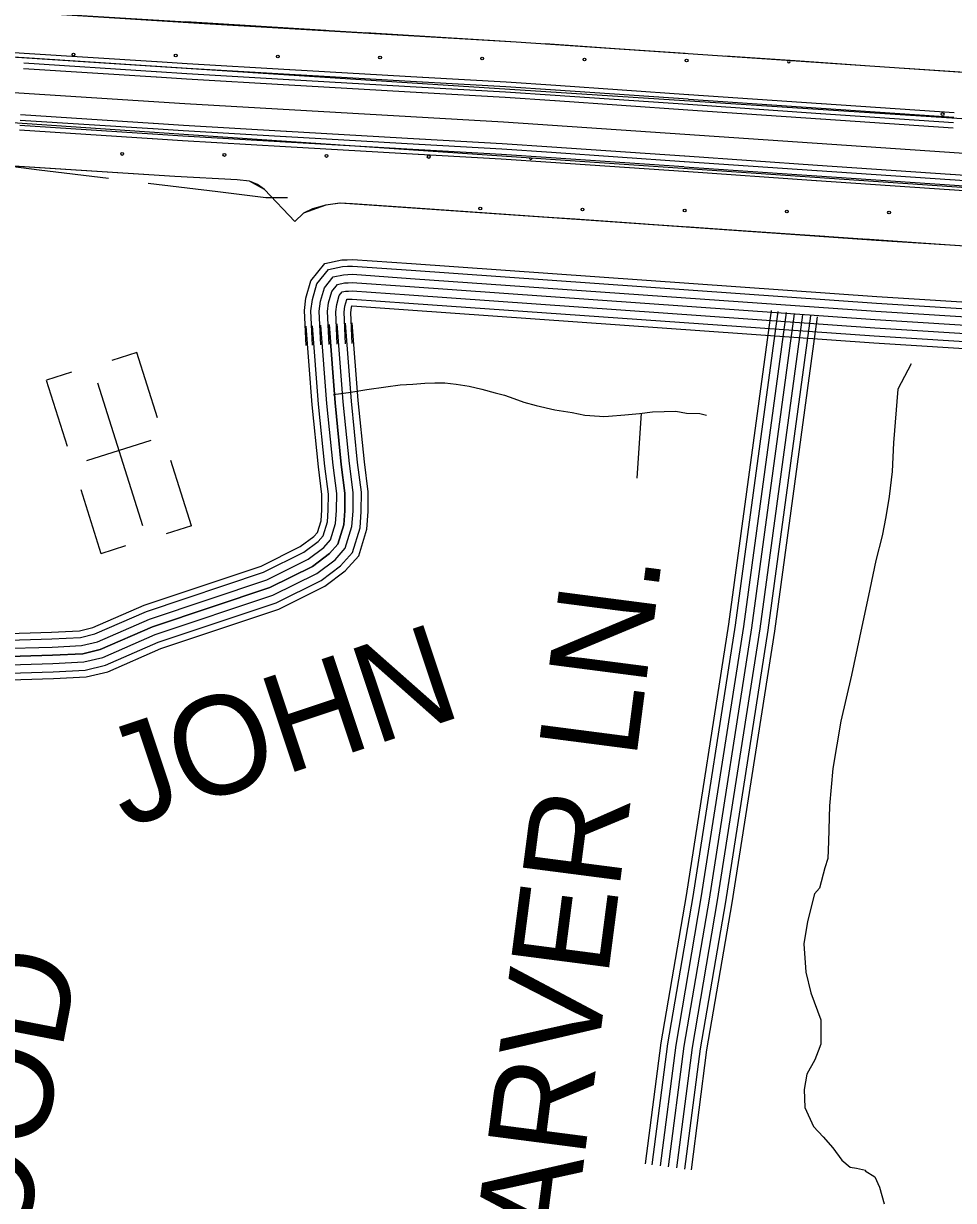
# Model space of a CAD drawing. Extents: x 1788175 to 1969470, y 584502 to 738744.
# Drawn here: x 1804703 to 1808203, y 664174 to 668600 of the extents above; entities that cross this region are included whole.
import ezdxf

# ---------------------------------------------------------------- set-up
doc = ezdxf.new("R2010")
doc.units = 0
for name, color, linetype in [('DESIGN - EROSION CONTROL - Devices', 7, 'Continuous'), ('DESIGN - ROW - Right-of-Way and Easement Labels', 7, 'Continuous'), ('DESIGN - SCRATCH - User 1', 7, 'Continuous'), ('DESIGN - TRANSPORTATION - Text', 7, 'Continuous'), ('DESIGN - UTILITIES - Cable (Underground) with Text', 7, 'Continuous'), ('SURVEY - CENTERLINE - Preliminary', 7, 'Continuous'), ('SURVEY - TRANSPORTATION - Roads', 7, 'Continuous'), ('SURVEY - VEGETATION - Features with Text', 7, 'Continuous')]:
    doc.layers.add(name, color=color, linetype=linetype)

msp = doc.modelspace()

# ---------------------------------------------------------------- linework, layer by layer
at = {"layer": 'DESIGN - EROSION CONTROL - Devices'}
for centre in [(1804891.6, 668483.1), (1805276.1, 668479.4), (1805660.7, 668475.6), (1806045.2, 668471.9), (1806429.8, 668468.2), (1806814.4, 668464.4), (1807198.9, 668460.7), (1808162.2, 668259.1), (1805074.6, 668109), (1805459.2, 668105.2), (1805843.7, 668101.5), (1806228.3, 668097.8), (1806422.4, 667903.6), (1806807, 667899.9), (1807191.5, 667896.1), (1807576.1, 667892.4), (1807960.6, 667888.7)]:
    msp.add_circle(centre, 5.28, dxfattribs=at)
for centre, start, end in [((1807583.5, 668457), 135.7944, 36.4425), ((1806612.8, 668094), 166.1356, 6.0817)]:
    msp.add_arc(centre, 5.28, start, end, dxfattribs=at)
at = {"layer": 'DESIGN - SCRATCH - User 1'}
for points in [[(1808664.9, 668387), (1806557.8, 668530), (1805384.9, 668598.1), (1804466.6, 668656.6), (1803677.1, 668706.8), (1802620.2, 668775.3), (1800681.4, 668914), (1800770.3, 668727.1)], [(1800770.3, 668727.1), (1809434.2, 668164.9), (1810234.9, 668118.5)], [(1800969.8, 668307.9), (1800885.7, 668484.5), (1810019.5, 667863.2)], [(1805724, 667855), (1805610.1, 667975.2), (1805583.5, 667994), (1805553.9, 668006.5), (1805507, 668011.2), (1805272.8, 668023.7), (1804393.1, 668080.1), (1803603.5, 668130.3), (1802569.9, 668197.2), (1800969.8, 668307.9)], [(1811666.5, 667588.8), (1811521.7, 667556.7), (1811453.2, 667549.4), (1811321.5, 667549.6), (1811097.5, 667563.7), (1810526.1, 667608.2), (1809694, 667671.1), (1807912.6, 667783), (1806161.4, 667906.7), (1805941.7, 667922), (1805893.4, 667924.4), (1805841, 667916.4), (1805790.9, 667902.7), (1805757, 667886.5), (1805724, 667855)]]:
    msp.add_lwpolyline(points, dxfattribs=at)
at = {"layer": 'DESIGN - TRANSPORTATION - Text'}
msp.add_lwpolyline([(1808044, 667319.3), (1807993.3, 667224.1), (1807977, 667022.3), (1807972.8, 666914.4), (1807960.6, 666820.5), (1807948.5, 666744.6), (1807934.4, 666672.7), (1807910.3, 666580.8), (1807888.1, 666472.9), (1807849.8, 666291.2), (1807819.6, 666149.3), (1807779.4, 665975.5), (1807749.1, 665797.7), (1807736.9, 665657.9), (1807732.6, 665524), (1807730.5, 665460.1), (1807718.5, 665424.1), (1807698.4, 665348.2), (1807680.3, 665326.3), (1807654.2, 665222.4), (1807640.1, 665138.5), (1807647.9, 665032.6), (1807665.8, 664954.7), (1807703.6, 664852.7), (1807703.5, 664800.8), (1807703.4, 664760.8), (1807693.4, 664734.8), (1807681.3, 664702.9), (1807651.3, 664649), (1807641.2, 664591), (1807643.1, 664523.1), (1807676.9, 664451.1), (1807712.9, 664413.1), (1807748.8, 664371.1), (1807782.7, 664325.1), (1807814.6, 664299.1), (1807838.6, 664295.1), (1807872.6, 664287.1), (1807870.6, 664285.1), (1807906.5, 664263), (1807924.5, 664223.1), (1807942.3, 664161.1)], dxfattribs=at)
at = {"layer": 'DESIGN - UTILITIES - Cable (Underground) with Text'}
for p, q in [((1805130.3, 667361.9), (1805035.2, 667331.9)), ((1805207.5, 667117.1), (1805130.2, 667361.9)), ((1804789.3, 667258.4), (1804867.8, 667009.7)), ((1804884.3, 667288.4), (1804789.9, 667258.6)), ((1805182.2, 667031.1), (1804940.4, 666954.7)), ((1805336, 666710.4), (1805258.2, 666956.5)), ((1804919.3, 666846.7), (1804995, 666606.9)), ((1805335.8, 666710.3), (1805240.9, 666680.4)), ((1804995.1, 666606.9), (1805088.8, 666636.5))]:
    msp.add_line(p, q, dxfattribs=at)
msp.add_lwpolyline([(1804982.1, 667248.6), (1805151.6, 666711.7)], dxfattribs=at)
at = {"layer": 'SURVEY - CENTERLINE - Preliminary'}
for points in [[(1820911.6, 669976.1), (1819959.6, 669862.9), (1819285.6, 669778.9), (1818471.7, 669687.3), (1818197.7, 669646.1), (1817901.7, 669609), (1817647.6, 669569.8), (1817303.6, 669516.8), (1816595.4, 669363), (1813251.8, 668401.6), (1812821.5, 668274.9), (1812669.5, 668231.4), (1812114.7, 668085.6), (1811965.2, 668057.6), (1811725.2, 668016.3), (1811385.2, 667981.3), (1811049.3, 667954.3), (1810455.5, 667960), (1806509.9, 668228.8), (1805310.6, 668298.1), (1804431.1, 668354.5), (1803641.6, 668404.7), (1802608.2, 668471.6), (1798199.8, 668776.1)], [(1804205.4, 668503.1), (1804439.6, 668488.2), (1804704.5, 668471.2)], [(1804206.5, 668520.6), (1804440.8, 668505.7), (1804705.6, 668488.7)], [(1804705.4, 668471.2), (1805204.4, 668439.2)], [(1804706.5, 668488.7), (1805205.5, 668456.6)], [(1805206.4, 668456.6), (1805319.8, 668449.3), (1805704.6, 668427.1)], [(1804703.7, 668430.9), (1805202.7, 668398.9)], [(1804704.1, 668451.2), (1805203.1, 668419.2)], [(1805204, 668419.2), (1805317.5, 668411.9), (1805702.4, 668389.6)], [(1805205.3, 668439.1), (1805318.7, 668431.8), (1805703.6, 668409.6)], [(1805704.5, 668409.5), (1806203.6, 668380.7)], [(1805705.5, 668427), (1806204.6, 668398.2)], [(1805203.6, 668398.9), (1805316.3, 668391.6), (1805702.2, 668369.3)], [(1805703.1, 668369.3), (1806202.2, 668340.4)], [(1805703.3, 668389.6), (1806202.5, 668360.7)], [(1806204.5, 668380.6), (1806518.3, 668362.5), (1806705, 668349.8)], [(1806205.6, 668398.1), (1806519.4, 668380), (1806706.2, 668367.3)], [(1806707.1, 668367.2), (1807205.9, 668333.2)], [(1806203.1, 668340.4), (1806515.8, 668322.3), (1806703.1, 668309.5)], [(1806203.4, 668360.7), (1806517.1, 668342.6), (1806703.6, 668329.8)], [(1806704.5, 668329.8), (1807203.4, 668295.8)], [(1806705.9, 668349.7), (1807204.7, 668315.8)], [(1807206.8, 668333.2), (1807705.7, 668299.2)], [(1806704, 668309.5), (1807202.9, 668275.5)], [(1807203.8, 668275.4), (1807702.6, 668241.4)], [(1807204.3, 668295.7), (1807703.1, 668261.7)], [(1807205.6, 668315.7), (1807704.5, 668281.7)], [(1807705.4, 668281.6), (1808204.2, 668247.7)], [(1807706.6, 668299.1), (1808205.4, 668265.1)], [(1804691.3, 668236.6), (1805190.2, 668204.6)], [(1804692.6, 668256.9), (1805191.5, 668224.8)], [(1807703.5, 668241.4), (1808202.4, 668207.4)], [(1807704, 668261.7), (1808202.9, 668227.7)], [(1804688.9, 668199.2), (1805187.8, 668167.2)], [(1804690, 668216.7), (1805189, 668184.6)], [(1805191.2, 668204.5), (1805304.4, 668197.3), (1805690.9, 668174.9)], [(1805192.4, 668224.8), (1805305.7, 668217.5), (1805692.1, 668195.2)], [(1805693, 668195.1), (1806192.2, 668166.3)], [(1805188.7, 668167.1), (1805302.2, 668159.8), (1805688.8, 668137.5)], [(1805189.9, 668184.6), (1805303.2, 668177.3), (1805689.8, 668155)], [(1805690.7, 668154.9), (1806189.8, 668126.1)], [(1805691.8, 668174.9), (1806191, 668146)], [(1806191.9, 668146), (1806503.6, 668128), (1806689.9, 668115.3)], [(1806193.1, 668166.2), (1806504.8, 668148.2), (1806691.3, 668135.5)], [(1805689.7, 668137.5), (1806188.8, 668108.6)], [(1806189.7, 668108.6), (1806501.2, 668090.6), (1806687.4, 668077.9)], [(1806190.7, 668126), (1806502.3, 668108), (1806688.5, 668095.3)], [(1806690.8, 668115.2), (1807189.6, 668081.2)], [(1806692.2, 668135.5), (1807191, 668101.5)], [(1807191.9, 668101.4), (1807690.8, 668067.4)], [(1806688.3, 668077.8), (1807187.1, 668043.8)], [(1806689.5, 668095.3), (1807188.3, 668061.3)], [(1807189.2, 668061.2), (1807688, 668027.2)], [(1807190.6, 668081.2), (1807689.4, 668047.2)], [(1807691.7, 668067.4), (1808190.5, 668033.4)], [(1807188, 668043.8), (1807686.8, 668009.8)], [(1807688.9, 668027.2), (1808187.8, 667993.2)], [(1807690.3, 668047.1), (1808189.1, 668013.1)], [(1808190.1, 668013.1), (1808688.9, 667979.1)], [(1808191.4, 668033.3), (1808690.3, 667999.3)], [(1807687.8, 668009.7), (1808186.6, 667975.7)], [(1808187.5, 667975.7), (1808686.3, 667941.7)], [(1808188.7, 667993.1), (1808687.5, 667959.1)]]:
    msp.add_lwpolyline(points, dxfattribs=at)
at = {"layer": 'SURVEY - TRANSPORTATION - Roads'}
for points in [[(1805766.5, 667388.4), (1805760.5, 667520.2), (1805766.3, 667566.4), (1805785, 667631.9), (1805837.3, 667697), (1805901, 667710.6), (1805922, 667711.2), (1805941.5, 667712.3), (1806163.6, 667696.9), (1807914.6, 667573.1), (1809696.1, 667461.3), (1810528.4, 667398.4), (1811099.7, 667353.8), (1811322.3, 667339.8), (1811450.9, 667339.7), (1811513.5, 667346.4), (1811898.5, 667449.7)], [(1805791.2, 667389.5), (1805785.3, 667519.3), (1805790.5, 667561.4), (1805807.4, 667620.3), (1805851.1, 667674.7), (1805903.9, 667686), (1805923, 667686.5), (1805941.3, 667687.5), (1806161.8, 667672.2), (1807912.9, 667548.5), (1809694.4, 667436.6), (1810526.5, 667373.7), (1811097.9, 667329.2), (1811321.5, 667315.1), (1811452.2, 667314.9), (1811518, 667322), (1811904.9, 667425.9)], [(1805822.1, 667390.9), (1805816.4, 667518), (1805821, 667555.2), (1805835.5, 667605.8), (1805868.3, 667646.7), (1805907.7, 667655.1), (1805924.2, 667655.6), (1805941.1, 667656.4), (1806159.7, 667641.3), (1807910.9, 667517.5), (1809692.3, 667405.7), (1810524.2, 667342.8), (1811095.7, 667298.2), (1811320.5, 667284.1), (1811453.8, 667283.9), (1811523.7, 667291.4), (1811912.9, 667395.9)], [(1805853.1, 667392.3), (1805847.5, 667516.8), (1805851.5, 667549), (1805863.5, 667591.2), (1805885.6, 667618.7), (1805911.4, 667624.2), (1805925.5, 667624.6), (1805940.8, 667625.4), (1806157.5, 667610.4), (1807908.8, 667486.6), (1809690.1, 667374.8), (1810521.8, 667311.9), (1811093.6, 667267.3), (1811319.5, 667253.1), (1811455.4, 667252.9), (1811529.4, 667260.9), (1811921, 667366)], [(1805853.1, 667392.3), (1805847.5, 667516.8), (1805851.5, 667549), (1805863.5, 667591.2), (1805885.6, 667618.7), (1805911.4, 667624.2), (1805925.5, 667624.6), (1805940.8, 667625.4), (1806157.5, 667610.4), (1807908.8, 667486.6), (1809690.1, 667374.8), (1810521.8, 667311.9), (1811093.6, 667267.3), (1811319.5, 667253.1), (1811455.4, 667252.9), (1811529.4, 667260.9), (1811921, 667366)], [(1805884.1, 667393.7), (1805878.5, 667515.6), (1805881.9, 667542.8), (1805891.6, 667576.7), (1805902.9, 667590.7), (1805915.1, 667593.3), (1805926.7, 667593.6), (1805940.6, 667594.3), (1806155.3, 667579.5), (1807906.7, 667455.7), (1809688, 667343.8), (1810519.4, 667281), (1811091.4, 667236.4), (1811318.5, 667222.1), (1811457.1, 667221.9), (1811535.1, 667230.3), (1811929, 667336)], [(1805915, 667395.2), (1805909.6, 667514.4), (1805912.4, 667536.6), (1805919.7, 667562.2), (1805919.9, 667562.4), (1805928, 667562.6), (1805940.3, 667563.3), (1806153.2, 667548.5), (1807904.7, 667424.7), (1809685.9, 667312.9), (1810517, 667250.1), (1811089.2, 667205.5), (1811317.5, 667191.1), (1811458.7, 667190.9), (1811540.8, 667199.7), (1811937, 667306.1)], [(1805940.7, 667396.3), (1805935.4, 667513.3), (1805937.7, 667531.4), (1805939.4, 667537.5), (1805940.1, 667537.5), (1806151.4, 667522.9), (1807903, 667399.1), (1809684.1, 667287.2), (1810515.1, 667224.4), (1811087.4, 667179.8), (1811316.7, 667165.4), (1811460.1, 667165.2), (1811545.6, 667174.4), (1811943.7, 667281.3)], [(1807517.1, 667520), (1807356.5, 666340.3), (1807196.9, 665320.9), (1807101.7, 664766.3), (1807042.7, 664311)], [(1807542.5, 667516.5), (1807381.9, 666336.5), (1807222.3, 665316.7), (1807127.1, 664762.5), (1807068.2, 664307.7)], [(1807573.3, 667512.3), (1807412.6, 666332), (1807252.9, 665311.7), (1807157.8, 664757.9), (1807098.9, 664303.7)], [(1807604, 667508.1), (1807443.3, 666327.6), (1807283.4, 665306.6), (1807188.5, 664753.2), (1807129.6, 664299.7)], [(1807604, 667508.1), (1807443.3, 666327.6), (1807283.4, 665306.6), (1807188.5, 664753.2), (1807129.6, 664299.7)], [(1807634.7, 667504), (1807474, 666323.1), (1807314, 665301.6), (1807219.1, 664748.6), (1807160.4, 664295.7)], [(1807665.4, 667499.8), (1807504.6, 666318.6), (1807344.6, 665296.6), (1807249.8, 664744), (1807191.1, 664291.7)], [(1807689.9, 667496.4), (1807529.1, 666315), (1807369, 665292.6), (1807274.2, 664740.3), (1807215.6, 664288.6)], [(1804606.1, 666304.5), (1804808.8, 666310.2), (1804913.7, 666315.7), (1804964.5, 666327.9), (1805157.2, 666412.1), (1805597.3, 666558.8), (1805744.9, 666632.4), (1805795.7, 666670.4), (1805809.4, 666685.6), (1805823, 666729.8), (1805825.7, 666770.7), (1805826.3, 666828.7), (1805813.1, 666931.9), (1805789.3, 667165.9), (1805766.6, 667460.9)], [(1804606.7, 666279.8), (1804809.7, 666285.6), (1804917.3, 666291.1), (1804972.4, 666304.4), (1805166, 666389), (1805606.7, 666535.9), (1805757.9, 666611.2), (1805812.5, 666652), (1805831.4, 666673.2), (1805847.4, 666725.3), (1805850.4, 666769.7), (1805851, 666830.2), (1805837.6, 666934.7), (1805813.9, 667168.1), (1805791.3, 667462.8)], [(1804607.5, 666248.8), (1804811, 666254.6), (1804921.7, 666260.3), (1804982.3, 666274.9), (1805177.2, 666360.1), (1805618.6, 666507.2), (1805774.2, 666584.7), (1805833.6, 666629.1), (1805859.1, 666657.6), (1805878.1, 666719.6), (1805881.4, 666768.5), (1805882, 666832), (1805868.4, 666938.2), (1805844.8, 667170.8), (1805822.2, 667465.2)], [(1805853.1, 667467.6), (1805875.7, 667173.6), (1805899.2, 666941.8), (1805913, 666833.8), (1805912.4, 666767.4), (1805908.8, 666714), (1805886.7, 666642), (1805854.6, 666606.1), (1805790.6, 666558.2), (1805630.5, 666478.5), (1805188.3, 666331.1), (1804992.2, 666245.4), (1804926.2, 666229.5), (1804812.2, 666223.6), (1804608.3, 666217.8)], [(1804608.3, 666217.8), (1804812.2, 666223.6), (1804926.2, 666229.5), (1804992.2, 666245.4), (1805188.3, 666331.1), (1805630.5, 666478.5), (1805790.6, 666558.2), (1805854.6, 666606.1), (1805886.7, 666642), (1805908.8, 666714), (1805912.4, 666767.4), (1805913, 666833.8), (1805899.2, 666941.8), (1805875.7, 667173.6), (1805853.1, 667467.6)], [(1804609, 666186.8), (1804813.4, 666192.6), (1804930.7, 666198.7), (1805002.1, 666215.9), (1805199.4, 666302.1), (1805642.3, 666449.8), (1805806.9, 666531.7), (1805875.7, 666583.1), (1805914.3, 666626.5), (1805939.5, 666708.3), (1805943.4, 666766.2), (1805944.1, 666835.7), (1805930, 666945.3), (1805906.6, 667176.3), (1805884, 667470)], [(1804609.8, 666155.8), (1804814.7, 666161.6), (1804935.1, 666167.8), (1805012, 666186.4), (1805210.6, 666273.2), (1805654.2, 666421), (1805823.2, 666505.2), (1805896.7, 666560.2), (1805942, 666610.9), (1805970.2, 666702.6), (1805974.4, 666765), (1805975.1, 666837.5), (1805960.8, 666948.8), (1805937.4, 667179.1), (1805914.9, 667472.3)], [(1804610.5, 666130.1), (1804815.7, 666135.9), (1804938.8, 666142.3), (1805020.3, 666161.9), (1805219.8, 666249.1), (1805664.1, 666397.2), (1805836.8, 666483.2), (1805914.2, 666541.1), (1805964.9, 666597.9), (1805995.7, 666697.9), (1806000.1, 666764), (1806000.8, 666839), (1805986.4, 666951.8), (1805963.1, 667181.4), (1805940.6, 667474.3)], [(1805870, 667204.5), (1805935.4, 667213.4), (1805995.5, 667223.4), (1806066.6, 667233.5), (1806120.7, 667240.3), (1806167.9, 667243), (1806214, 667247.7), (1806251.1, 667248.3), (1806289.3, 667247.9), (1806331.5, 667243.6), (1806380.8, 667235.4), (1806428.2, 667225.1), (1806478.6, 667210.9), (1806512.9, 667202.4), (1806548.2, 667189), (1806586.6, 667175.6), (1806633, 667163.3), (1806702.5, 667146.4), (1806767.9, 667136.5), (1806816.3, 667127.2), (1806871.6, 667123.1), (1806885.4, 667122)], [(1806885.4, 667122), (1806904.6, 667123.4), (1806965.8, 667128.3), (1807021.9, 667133.2), (1807071, 667139), (1807114.2, 667140.6), (1807158.3, 667142.3), (1807198.6, 667134), (1807248.8, 667132.8), (1807273.2, 667127.3)], [(1807028.3, 667134), (1807010.9, 666889.6)]]:
    msp.add_lwpolyline(points, dxfattribs=at)
at = {"layer": 'SURVEY - VEGETATION - Features with Text'}
for points in [[(1808959.9, 668367), (1808664.9, 668387), (1806557.8, 668530), (1804466.6, 668656.6), (1800681.4, 668914), (1800969.8, 668307.9)], [(1805577.2, 668589.4), (1805313.7, 668605.3)], [(1805840.7, 668573.4), (1805577.2, 668589.4)], [(1806253.9, 668548.4), (1805990.4, 668564.3)], [(1806517.5, 668532.4), (1806253.9, 668548.4)], [(1806930.5, 668504.7), (1806667.1, 668522.6)], [(1807193.9, 668486.8), (1806930.5, 668504.7)], [(1807607, 668458.8), (1807343.6, 668476.7)], [(1807870.4, 668440.9), (1807607, 668458.8)], [(1808283.4, 668412.9), (1808020, 668430.8)], [(1811514.7, 667556), (1811411.6, 667549.5), (1811185.8, 667558.4), (1810808.5, 667586.2), (1810258.4, 667628.5), (1809441.3, 667687), (1808226.4, 667763.3), (1806619.9, 667874.3), (1805894.7, 667924.4), (1805841.2, 667916.4), (1805757, 667886.5), (1805724, 667855), (1805610.1, 667975.2), (1805553.9, 668006.5), (1805507, 668011.2), (1805272.8, 668023.7), (1804627.3, 668065.1), (1802616.2, 668194.2), (1800969.8, 668307.9)], [(1804761.8, 668048.7), (1804627.3, 668065.1), (1804499.1, 668073.3)], [(1805023.8, 668016.6), (1804761.8, 668048.7)], [(1805434.8, 667966.4), (1805172.7, 667998.4)], [(1805697.4, 667944.3), (1805615.6, 667944.3), (1805434.8, 667966.4)], [(1806103.3, 667910), (1805894.7, 667924.4), (1805841.2, 667916.4), (1805840.5, 667916.8)], [(1806366.6, 667891.8), (1806103.3, 667910)], [(1806779.7, 667863.3), (1806619.9, 667874.3), (1806516.3, 667881.5)], [(1807043, 667845.1), (1806779.7, 667863.3)], [(1807456, 667816.5), (1807192.7, 667834.7)], [(1807719.4, 667798.3), (1807456, 667816.5)], [(1808132.4, 667769.8), (1807869.1, 667788)], [(1808395.9, 667752.6), (1808226.4, 667763.3), (1808132.4, 667769.8)]]:
    msp.add_lwpolyline(points, dxfattribs=at)

# ---------------------------------------------------------------- texts
at = {"layer": 'DESIGN - ROW - Right-of-Way and Easement Labels'}
for s, height, rotation, p in [('W. CARVER LN.', 369.999, 82.6108, (1806629.9, 662911.1)), ('JOHN', 370, 18.435, (1805085.6, 665572.7)), ('JAYWOOD', 370, 79.1166, (1804442.2, 662626.7))]:
    msp.add_text(s, height=height, rotation=rotation, dxfattribs=at).set_placement(p)

doc.saveas('drawing.dxf')
